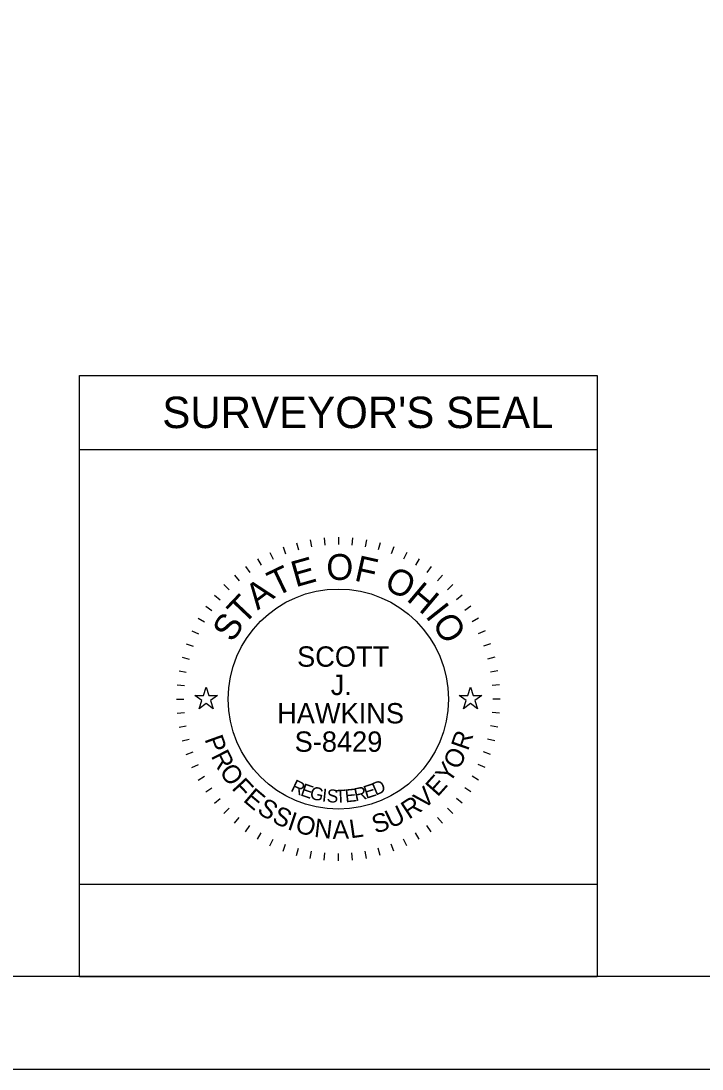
# Model space of a CAD drawing. Extents: x 0 to 34, y 0 to 22.
# Drawn here: x 14.29 to 17.97, y 0 to 5.67 of the extents above; entities that cross this region are included whole.
import ezdxf

# ---------------------------------------------------------------- set-up
doc = ezdxf.new("R2010")
doc.units = 0
for name, color, linetype in [('SH_Border', 7, 'Continuous'), ('SH_Cut_Line', 7, 'Continuous'), ('SH_Data', 7, 'Continuous'), ('SH_Seal', 7, 'Continuous')]:
    doc.layers.add(name, color=color, linetype=linetype)

msp = doc.modelspace()

# ---------------------------------------------------------------- linework, layer by layer
at = {"layer": 'SH_Border'}
msp.add_lwpolyline([(1.5, 21.5), (33.5, 21.5), (33.5, 0.5), (1.5, 0.5)], close=True, dxfattribs=at)
at = {"layer": 'SH_Cut_Line'}
msp.add_lwpolyline([(0, 0), (34, 0), (34, 22), (0, 22)], close=True, dxfattribs=at)
at = {"layer": 'SH_Data'}
for p, q in [((14.6061, 0.5), (14.6061, 3.75)), ((14.6061, 3.75), (17.4061, 3.75)), ((17.4061, 3.75), (17.4061, 0.5)), ((14.6061, 3.35), (17.4061, 3.35)), ((14.6061, 0.5), (17.4061, 0.5))]:
    msp.add_line(p, q, dxfattribs=at)
msp.add_lwpolyline([(14.6061, 0.5), (14.6061, 1), (17.4061, 1), (17.4061, 0.5)], close=True, dxfattribs=at)
at = {"layer": 'SH_Seal'}
for p, q in [((15.7797, 2.8452), (15.79, 2.8065)), ((15.8542, 2.8617), (15.8611, 2.8223)), ((15.9299, 2.8717), (15.9333, 2.8318)), ((16.0061, 2.875), (16.0061, 2.835)), ((16.0824, 2.8717), (16.0789, 2.8318)), ((16.1581, 2.8617), (16.1511, 2.8223)), ((16.2326, 2.8452), (16.2222, 2.8065)), ((15.6363, 2.793), (15.6532, 2.7568)), ((15.7069, 2.8222), (15.7205, 2.7846)), ((16.3054, 2.8222), (16.2917, 2.7846)), ((16.3759, 2.793), (16.359, 2.7568)), ((15.5686, 2.7578), (15.5886, 2.7231)), ((16.4436, 2.7578), (16.4236, 2.7231)), ((15.4437, 2.6703), (15.4694, 2.6396)), ((15.5042, 2.7168), (15.5272, 2.684)), ((16.508, 2.7168), (16.4851, 2.684)), ((16.5686, 2.6703), (16.5428, 2.6396)), ((15.3874, 2.6187), (15.4157, 2.5904)), ((16.6248, 2.6187), (16.5966, 2.5904)), ((15.3358, 2.5624), (15.3665, 2.5367)), ((16.6764, 2.5624), (16.6458, 2.5367)), ((15.2894, 2.5019), (15.3221, 2.4789)), ((16.7229, 2.5019), (16.6901, 2.4789)), ((15.2483, 2.4375), (15.283, 2.4175)), ((16.7639, 2.4375), (16.7293, 2.4175)), ((15.2131, 2.3698), (15.2494, 2.3529)), ((16.7991, 2.3698), (16.7629, 2.3529)), ((15.1839, 2.2993), (15.2215, 2.2856)), ((16.8284, 2.2993), (16.7908, 2.2856)), ((15.1609, 2.2265), (15.1996, 2.2161)), ((16.8513, 2.2265), (16.8127, 2.2161)), ((15.1444, 2.1519), (15.1838, 2.145)), ((16.8678, 2.1519), (16.8284, 2.145)), ((15.1345, 2.0763), (15.1743, 2.0728)), ((16.8778, 2.0763), (16.8379, 2.0728)), ((15.1311, 2), (15.1711, 2)), ((16.8811, 2), (16.8411, 2)), ((15.1345, 1.9237), (15.1743, 1.9272)), ((16.8778, 1.9237), (16.8379, 1.9272)), ((15.1444, 1.8481), (15.1838, 1.855)), ((16.8678, 1.8481), (16.8284, 1.855)), ((15.1609, 1.7735), (15.1996, 1.7839)), ((16.8513, 1.7735), (16.8127, 1.7839)), ((15.1839, 1.7007), (15.2215, 1.7144)), ((16.8284, 1.7007), (16.7908, 1.7144)), ((15.2131, 1.6302), (15.2494, 1.6471)), ((16.7991, 1.6302), (16.7629, 1.6471)), ((15.2483, 1.5625), (15.283, 1.5825)), ((16.7639, 1.5625), (16.7293, 1.5825)), ((15.2894, 1.4981), (15.3221, 1.5211)), ((16.7229, 1.4981), (16.6901, 1.5211)), ((15.3358, 1.4376), (15.3665, 1.4633)), ((16.6764, 1.4376), (16.6458, 1.4633)), ((15.3874, 1.3813), (15.4157, 1.4096)), ((15.4437, 1.3297), (15.4694, 1.3604)), ((16.5686, 1.3297), (16.5428, 1.3604)), ((16.6248, 1.3813), (16.5966, 1.4096)), ((15.5042, 1.2832), (15.5272, 1.316)), ((16.508, 1.2832), (16.4851, 1.316)), ((15.5686, 1.2422), (15.5886, 1.2769)), ((16.4436, 1.2422), (16.4236, 1.2769)), ((15.6363, 1.207), (15.6532, 1.2432)), ((15.7069, 1.1778), (15.7205, 1.2154)), ((15.7797, 1.1548), (15.79, 1.1935)), ((16.2326, 1.1548), (16.2222, 1.1935)), ((16.3054, 1.1778), (16.2917, 1.2154)), ((16.3759, 1.207), (16.359, 1.2432)), ((15.8542, 1.1383), (15.8611, 1.1777)), ((15.9299, 1.1283), (15.9333, 1.1682)), ((16.0061, 1.125), (16.0061, 1.165)), ((16.0824, 1.1283), (16.0789, 1.1682)), ((16.1581, 1.1383), (16.1511, 1.1777))]:
    msp.add_line(p, q, dxfattribs=at)
for points in [[(15.2297, 2.02), (15.2766, 2.02), (15.2911, 2.0645), (15.3056, 2.02), (15.3525, 2.02), (15.3146, 1.9924), (15.3291, 1.9478), (15.2911, 1.9754), (15.2531, 1.9478), (15.2676, 1.9924)], [(16.6597, 2.02), (16.7066, 2.02), (16.7211, 2.0645), (16.7356, 2.02), (16.7825, 2.02), (16.7446, 1.9924), (16.7591, 1.9478), (16.7211, 1.9754), (16.6831, 1.9478), (16.6976, 1.9924)]]:
    msp.add_lwpolyline(points, close=True, dxfattribs=at)
msp.add_circle((16.0061, 2), 0.595, dxfattribs=at)

# ---------------------------------------------------------------- texts
at = {"layer": 'SH_Data'}
msp.add_text("SURVEYOR'S SEAL", height=0.17, dxfattribs=at).set_placement((15.054, 3.465))
at = {"layer": 'SH_Seal'}
for s, height, rotation, p in [('O', 0.14, 359.7812, (15.9408, 2.6443)), ('T', 0.14, 25.7167, (15.6678, 2.5518)), ('E', 0.14, 15.7571, (15.7745, 2.6038)), ('F', 0.14, 347.4362, (16.0872, 2.6417)), ('O', 0.14, 332.2586, (16.2459, 2.6015)), ('A', 0.14, 36.4747, (15.5695, 2.4781)), ('H', 0.14, 319.9136, (16.3693, 2.5361)), ('T', 0.14, 46.4344, (15.4944, 2.3964)), ('I', 0.14, 308.367, (16.4726, 2.4483)), ('S', 0.14, 57.1924, (15.4342, 2.3014)), ('O', 0.14, 303.1491, (16.5083, 2.4089)), ('R', 0.1, 70.983, (16.707, 1.7167)), ('P', 0.1, 289.7431, (15.2815, 1.7841)), ('R', 0.1, 296.9802, (15.3154, 1.6927)), ('O', 0.1, 62.7428, (16.6562, 1.6133)), ('O', 0.1, 304.7158, (15.3593, 1.6079)), ('Y', 0.1, 55.5058, (16.6061, 1.54)), ('E', 0.1, 48.2687, (16.5427, 1.4673)), ('F', 0.1, 312.956, (15.4254, 1.5158)), ('R', 0.07, 334.487, (15.7436, 1.5051)), ('E', 0.07, 341.04, (15.7968, 1.4801)), ('E', 0.07, 17.6836, (16.1559, 1.4602)), ('D', 0.07, 23.3052, (16.2071, 1.477)), ('V', 0.1, 41.0316, (16.4676, 1.4007)), ('E', 0.1, 319.6885, (15.4869, 1.4504)), ('G', 0.07, 347.4752, (15.8476, 1.4618)), ('I', 0.07, 353.7858, (15.9152, 1.4468)), ('S', 0.07, 356.8926, (15.9419, 1.4429)), ('T', 0.07, 3.0061, (15.9918, 1.4387)), ('E', 0.07, 6.0117, (16.0451, 1.4412)), ('R', 0.07, 11.9184, (16.0986, 1.4474)), ('S', 0.1, 326.9255, (15.5616, 1.3885)), ('U', 0.1, 25.5604, (16.2894, 1.2986)), ('R', 0.1, 33.296, (16.3876, 1.3473)), ('S', 0.1, 334.1626, (15.6421, 1.3374)), ('I', 0.1, 341.3997, (15.7252, 1.2979)), ('O', 0.1, 345.1351, (15.7679, 1.2821)), ('S', 0.1, 18.3234, (16.2066, 1.2711)), ('N', 0.1, 353.3752, (15.8721, 1.2555)), ('A', 0.1, 1.1108, (15.9753, 1.2443)), ('L', 0.1, 8.3479, (16.0725, 1.2467))]:
    msp.add_text(s, height=height, rotation=rotation, dxfattribs=at).set_placement(p)
for s, p in [('SCOTT', (15.7828, 2.1749)), ('J.', (15.9649, 2.0216)), ('HAWKINS', (15.6748, 1.8684)), ('S-8429', (15.7697, 1.7151))]:
    msp.add_text(s, height=0.11, dxfattribs=at).set_placement(p)

doc.saveas('drawing.dxf')
